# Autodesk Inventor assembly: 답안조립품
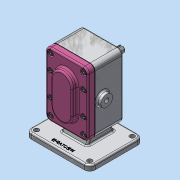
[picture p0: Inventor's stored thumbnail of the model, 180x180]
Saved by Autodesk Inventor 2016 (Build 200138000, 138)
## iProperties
Created: 2020-04
Part Number: 답안조립품
Document SubType Name: Assembly
Designer: MIRAE
Author: MIRAE
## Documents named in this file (11)
- C:\Users\MIRAE\Desktop\700407V1025\답안조립품.iam
- C:\Users\MIRAE\Desktop\700407V1025\본체.ipt
- C:\Users\MIRAE\Desktop\700407V1025\메인축.ipt
- C:\Users\MIRAE\Desktop\700407V1025\키 6 x 6 x 18.ipt
- C:\Users\MIRAE\Desktop\700407V1025\스퍼기어.ipt
- C:\Users\MIRAE\Desktop\700407V1025\서브축.ipt
- C:\Users\MIRAE\Desktop\700407V1025\베어링부시.ipt
- C:\Users\MIRAE\Desktop\700407V1025\개스킷.ipt
- C:\Users\MIRAE\Desktop\700407V1025\커버.ipt
- C:\Users\MIRAE\Desktop\700407V1025\볼트 M5.ipt
- C:\Users\MIRAE\Desktop\700407V1025\오일 실 16 28 7.ipt
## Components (1 placed, 1 different names)
1. 개스킷:1
